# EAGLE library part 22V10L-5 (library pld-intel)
PLD
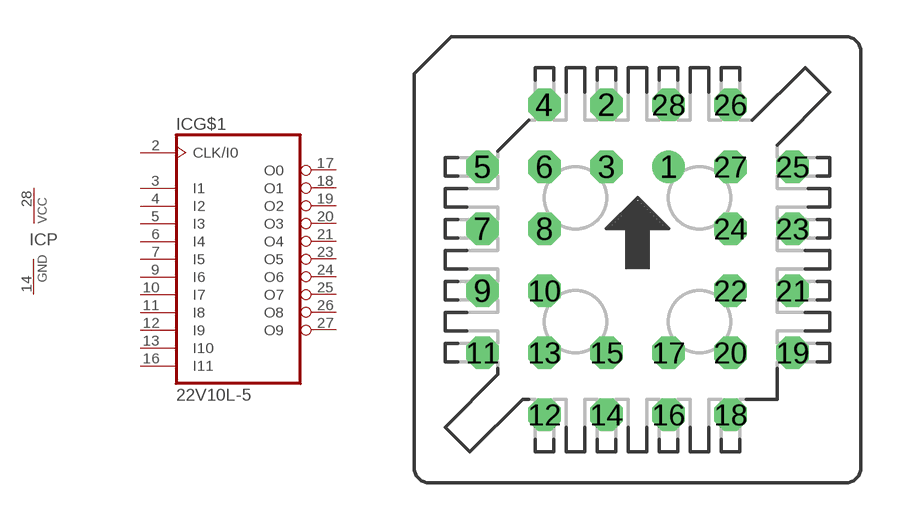
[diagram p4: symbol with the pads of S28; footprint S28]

Designator prefix IC; gates G$1=22V10L-5 P=PWRN

## 22V10L-5 (OC_FARNELL: unknown; OC_NEWARK: unknown)  [S28]
2  G$1:CLK/I0  in
3  G$1:I1  in
4  G$1:I2  in
5  G$1:I3  in
6  G$1:I4  in
7  G$1:I5  in
9  G$1:I6  in
10  G$1:I7  in
11  G$1:I8  in
12  G$1:I9  in
13  G$1:I10  in
14  P:GND  pwr
16  G$1:I11  in
17  G$1:O0
18  G$1:O1
19  G$1:O2
20  G$1:O3
21  G$1:O4
23  G$1:O5
24  G$1:O6
25  G$1:O7
26  G$1:O8
27  G$1:O9
28  P:VCC  pwr

## Footprint S28 (pad centres in mm)
PLCC SOCKET
drill 0.813 round: 1 1.27,3.81
drill 0.813 octagon: 2 -1.27,6.35; 3 -1.27,3.81; 4 -3.81,6.35; 5 -6.35,3.81; 6 -3.81,3.81; 7 -6.35,1.27; 8 -3.81,1.27; 9 -6.35,-1.27; 10 -3.81,-1.27; 11 -6.35,-3.81; 12 -3.81,-6.35; 13 -3.81,-3.81; 14 -1.27,-6.35; 15 -1.27,-3.81; 16 1.27,-6.35; 17 1.27,-3.81; 18 3.81,-6.35; 19 6.35,-3.81; 20 3.81,-3.81; 21 6.35,-1.27; 22 3.81,-1.27; 23 6.35,1.27; 24 3.81,1.27; 25 6.35,3.81; 26 3.81,6.35; 27 3.81,3.81; 28 1.27,6.35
